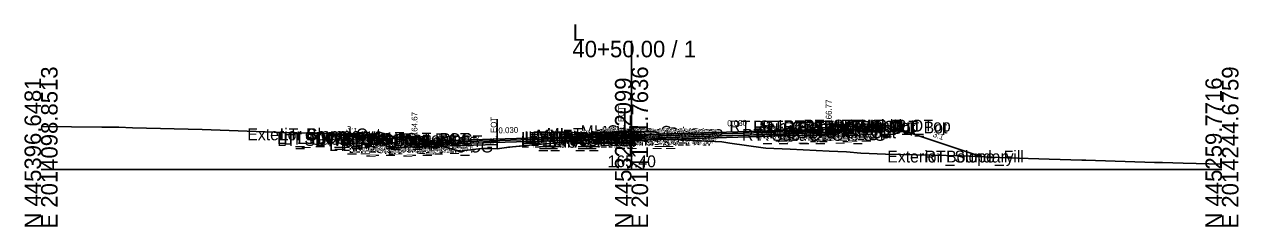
# Model space of a CAD drawing. Extents: x -26 to 4203, y -10 to 9526.
# Drawn here: x 2997.2 to 3202.8, y 490.3 to 524.6 of the extents above; entities that cross this region are included whole.
import ezdxf

# ---------------------------------------------------------------- set-up
doc = ezdxf.new("R2010")
doc.units = 0
for name, color, linetype in [('Default', 7, 'Continuous'), ('Exist CMT Pavement', 7, 'Continuous'), ('Exist Cross Section Cell', 7, 'Continuous'), ('Exist XS Center Line Elevation Label', 7, 'Continuous'), ('Exist XS Ground Line', 7, 'Continuous'), ('Prop CMT Conc Surface', 7, 'Continuous'), ('Prop CMT Concrete Structures', 7, 'Continuous'), ('Prop CMT Pvmt Course 1', 7, 'Continuous'), ('Prop CMT Pvmt Course 1 CG', 7, 'Continuous'), ('Prop CMT Pvmt Course 2', 7, 'Continuous'), ('Prop CMT Pvmt Course 3', 7, 'Continuous'), ('Prop CMT Pvmt Surface', 7, 'Continuous'), ('Prop CMT Slope Grass', 7, 'Continuous'), ('Prop CMT Subgrade Earthwork', 7, 'Continuous'), ('Prop XS Hydro Elevations', 7, 'Continuous'), ('Prop XS Label Text', 7, 'Continuous'), ('Prop XS SE Text', 7, 'Continuous'), ('Prop XS Side Slope Text', 7, 'Continuous'), ('Scratch_Level_0', 7, 'Continuous')]:
    doc.layers.add(name, color=color, linetype=linetype)

msp = doc.modelspace()

# ---------------------------------------------------------------- linework, layer by layer
at = {"layer": 'Exist CMT Pavement'}
for p, q in [((3079.85, 503.84), (3082.7, 504.14)), ((3082.7, 504.14), (3086.82, 504.5)), ((3086.82, 504.5), (3090.1, 504.8)), ((3090.1, 504.8), (3092.09, 504.95)), ((3092.09, 504.95), (3096.77, 505.26)), ((3096.77, 505.26), (3097.28, 505.29)), ((3097.28, 505.29), (3098.85, 505.39)), ((3077.27, 503.53), (3078.46, 503.71)), ((3078.46, 503.71), (3079.85, 503.84))]:
    msp.add_line(p, q, dxfattribs=at)
at = {"layer": 'Exist Cross Section Cell'}
for p, q in [((3100, 500), (3100, 521.83)), ((3000, 500), (3100, 500)), ((3100, 500), (3200, 500))]:
    msp.add_line(p, q, dxfattribs=at)
at = {"layer": 'Exist XS Ground Line'}
msp.add_lwpolyline([(3000, 507.28), (3010.27, 507.21), (3011.83, 507.19), (3013.19, 507.18), (3015.47, 507.09), (3027.31, 506.78), (3041.03, 506.27), (3047.94, 506.11), (3053.26, 505.85), (3063.03, 505.4), (3070.79, 503.11), (3071.75, 503.24), (3074.62, 503.55), (3075.76, 503.56), (3077.27, 503.53), (3078.46, 503.71), (3079.19, 503.77), (3079.85, 503.84), (3081.17, 503.98), (3082.7, 504.14), (3083.24, 504.19), (3086.82, 504.5), (3089.34, 504.74), (3090.1, 504.8), (3092.09, 504.95), (3093.62, 505.06), (3096.77, 505.26), (3097.28, 505.29), (3098.85, 505.39), (3100, 505.4), (3100.4, 505.4), (3100.97, 505.39), (3103.61, 505.31), (3103.96, 505.3), (3104.55, 505.22), (3105.08, 505.21), (3105.76, 505.17), (3115.32, 504.7), (3116.67, 504.5), (3122.32, 503.66), (3122.77, 503.64), (3126.89, 503.45), (3133.5, 503.11), (3136.41, 502.98), (3138.82, 502.8), (3142.99, 502.62), (3150.76, 502.43), (3155.9, 502.33), (3163.7, 502.01), (3170.71, 501.78), (3176.27, 501.59), (3176.96, 501.57), (3188.56, 501.22), (3189.95, 501.17), (3193.42, 501.07), (3200, 500.89)], dxfattribs=at)
at = {"layer": 'Prop CMT Conc Surface'}
for points in [[(3131.4, 506.79), (3133.4, 506.77)], [(3133.4, 506.77), (3133.4, 507.27), (3133.9, 507.27)], [(3137.9, 507.36), (3142.9, 507.46)], [(3058.75, 505.25), (3053.75, 505.35)], [(3063.25, 504.67), (3063.25, 505.16), (3062.75, 505.16)], [(3065.25, 504.8), (3063.25, 504.67)]]:
    msp.add_lwpolyline(points, dxfattribs=at)
at = {"layer": 'Prop CMT Concrete Structures'}
for points in [[(3104.62, 505.99), (3104.61, 506.15), (3103.86, 506.4), (3098.31, 506.51), (3092.76, 506.02), (3092.01, 505.77), (3092, 505.61)], [(3092, 505.61), (3104.62, 505.99)], [(3131.4, 506.79), (3133.4, 506.77), (3133.4, 507.27), (3133.9, 507.27)], [(3133.9, 507.27), (3133.9, 506.28), (3131.4, 506.21)], [(3131.4, 506.21), (3131.4, 506.79)], [(3142.9, 507.46), (3137.9, 507.36)], [(3137.9, 507.36), (3137.9, 507.03)], [(3137.9, 507.03), (3142.9, 507.13)], [(3142.9, 507.13), (3142.9, 507.46)], [(3053.75, 505.02), (3053.75, 505.35)], [(3053.75, 505.35), (3058.75, 505.25)], [(3058.75, 504.92), (3053.75, 505.02)], [(3058.75, 505.25), (3058.75, 504.92)], [(3065.25, 504.8), (3063.25, 504.67), (3063.25, 505.16), (3062.75, 505.16)], [(3062.75, 505.16), (3062.75, 504.15), (3065.25, 504.22)], [(3065.25, 504.22), (3065.25, 504.8)]]:
    msp.add_lwpolyline(points, dxfattribs=at)
at = {"layer": 'Prop CMT Pvmt Course 1'}
for points in [[(3092, 505.61), (3104.62, 505.99)], [(3104.62, 505.99), (3131.4, 506.79)], [(3131.4, 506.54), (3104.62, 505.74)], [(3104.62, 505.99), (3104.62, 505.74)], [(3104.62, 505.74), (3104.62, 505.99)], [(3131.4, 506.79), (3131.4, 506.54)], [(3092, 505.61), (3065.25, 504.8)], [(3065.25, 504.55), (3092, 505.36)], [(3065.25, 504.8), (3065.25, 504.55)], [(3104.62, 505.74), (3092, 505.36)], [(3092, 505.36), (3092, 505.61)], [(3092, 505.36), (3092, 505.61)]]:
    msp.add_lwpolyline(points, dxfattribs=at)
for points in [[(3092, 505.36), (3092, 505.48), (3092, 505.48), (3092, 505.36)], [(3104.62, 505.74), (3104.62, 505.86), (3104.62, 505.86), (3104.62, 505.74)]]:
    msp.add_lwpolyline(points, close=True, dxfattribs=at)
at = {"layer": 'Prop CMT Pvmt Course 1 CG'}
for points in [[(3131.4, 506.21), (3134.4, 506.3), (3134.72, 505.97)], [(3131.4, 505.87), (3131.4, 506.21)], [(3065.25, 504.22), (3062.25, 504.13), (3061.91, 503.79)], [(3065.25, 503.89), (3065.25, 504.22)], [(3134.72, 505.97), (3131.4, 505.87)], [(3061.91, 503.79), (3065.25, 503.89)]]:
    msp.add_lwpolyline(points, dxfattribs=at)
at = {"layer": 'Prop CMT Pvmt Course 2'}
for points in [[(3104.62, 505.74), (3131.4, 506.54)], [(3131.4, 506.21), (3104.62, 505.4)], [(3131.4, 506.54), (3131.4, 506.21)], [(3092, 505.36), (3065.25, 504.55)], [(3065.25, 504.22), (3092, 505.02)], [(3065.25, 504.55), (3065.25, 504.22)], [(3092, 505.36), (3104.62, 505.74)], [(3104.62, 505.4), (3092, 505.02)], [(3092, 505.02), (3092, 505.36)], [(3092, 505.02), (3092, 505.36)], [(3104.62, 505.74), (3104.62, 505.4)], [(3104.62, 505.4), (3104.62, 505.74)]]:
    msp.add_lwpolyline(points, dxfattribs=at)
at = {"layer": 'Prop CMT Pvmt Course 3'}
for points in [[(3104.62, 505.4), (3131.4, 506.21)], [(3131.4, 506.21), (3131.4, 505.87)], [(3092, 505.02), (3065.25, 504.22)], [(3065.25, 503.89), (3077.27, 504.25)], [(3065.25, 504.22), (3065.25, 503.89)], [(3092, 505.02), (3104.62, 505.4)], [(3104.62, 505.07), (3098.85, 504.9)], [(3131.4, 505.87), (3104.62, 505.07)], [(3104.62, 505.4), (3104.62, 505.07)], [(3104.62, 505.07), (3104.62, 505.4)]]:
    msp.add_lwpolyline(points, dxfattribs=at)
at = {"layer": 'Prop CMT Pvmt Surface'}
for points in [[(3092, 505.61), (3104.62, 505.99)], [(3104.62, 505.99), (3131.4, 506.79)], [(3092, 505.61), (3065.25, 504.8)]]:
    msp.add_lwpolyline(points, dxfattribs=at)
at = {"layer": 'Prop CMT Slope Grass'}
for points in [[(3133.9, 507.27), (3142.9, 507.45)], [(3142.9, 507.45), (3143.4, 507.46), (3159.18, 502.2)], [(3062.75, 505.16), (3053.25, 505.35), (3051.51, 505.94)]]:
    msp.add_lwpolyline(points, dxfattribs=at)
at = {"layer": 'Prop CMT Subgrade Earthwork'}
for p, q in [((3077.27, 504.25), (3077.27, 503.53)), ((3098.85, 504.9), (3098.85, 505.39))]:
    msp.add_line(p, q, dxfattribs=at)
for points in [[(3131.4, 505.87), (3134.72, 505.97), (3136.06, 507.31)], [(3065.25, 503.89), (3061.91, 503.79), (3060.48, 505.21)], [(3077.27, 504.25), (3065.25, 503.89)], [(3098.85, 504.9), (3104.62, 505.07)], [(3104.62, 505.07), (3131.4, 505.87)]]:
    msp.add_lwpolyline(points, dxfattribs=at)
at = {"layer": 'Prop XS Label Text'}
for p, q in [((3098.85, 510.39), (3098.85, 505.39)), ((3077.27, 508.53), (3077.27, 503.53))]:
    msp.add_line(p, q, dxfattribs=at)

# ---------------------------------------------------------------- texts
at = {"layer": 'Default'}
msp.add_text('-', height=0.0001, dxfattribs=at).set_placement((3000, 500))
at = {"layer": 'Exist Cross Section Cell'}
for s, p in [('L', (3090, 521.83)), ('40+50.00 / 1', (3090, 519.03))]:
    msp.add_text(s, height=2.8, dxfattribs=at).set_placement(p)
for s, p in [('E 2014098.8513', (3002.8, 490)), ('E 2014171.7636', (3102.8, 490)), ('E 2014244.6759', (3202.8, 490)), ('N 445396.6481', (3000, 490)), ('N 445328.2099', (3100, 490)), ('N 445259.7716', (3200, 490))]:
    msp.add_text(s, height=2.8, rotation=90, dxfattribs=at).set_placement(p)
at = {"layer": 'Exist XS Center Line Elevation Label'}
msp.add_text('165.40', height=2, dxfattribs=at).set_placement((3095.95, 500.4))
at = {"layer": 'Prop XS Hydro Elevations'}
for s, p in [('166.77', (3133.9, 507.77)), ('164.67', (3063.75, 505.67))]:
    msp.add_text(s, height=1, rotation=90, dxfattribs=at).set_placement(p)
at = {"layer": 'Prop XS Label Text'}
for p in [(3098.75, 506.41), (3077.17, 504.56)]:
    msp.add_text('E. EOT', height=1, rotation=90, dxfattribs=at).set_placement(p)
at = {"layer": 'Prop XS SE Text'}
for rotation, p in [(1.718, (3116.23, 507.33)), (1.7173, (3077.48, 506.13))]:
    msp.add_text('0.030', height=1, rotation=rotation, dxfattribs=at).set_placement(p)
at = {"layer": 'Prop XS Side Slope Text'}
for p in [(3051.59, 506.54), (3150.95, 505.58)]:
    msp.add_text('3:1', height=1, rotation=341.5651, dxfattribs=at).set_placement(p)
at = {"layer": 'Scratch_Level_0'}
for s, p in [('RT_Sub_Trench_Out_DLT', (3116.58, 506.31)), ('RT_CG_Top_Face', (3120.61, 506.27)), ('RT_CG_Top_BOC', (3122.13, 506.27)), ('RT_SDWK_In_Top', (3125.71, 506.36)), ('RT_SDWK_In_Bot', (3125.74, 506.03)), ('RT_SDWK_Out_Top', (3129.09, 506.46)), ('RT_SDWK_Out_Bot', (3129.12, 506.13)), ('RT_Shld_O', (3135.43, 506.45)), ('CSLP_Pnt', (3136.26, 506.46)), ('Exterior Boundary', (3034.93, 504.97)), ('LT_SDWK_Out_Top', (3039.99, 504.36)), ('LT_SDWK_Out_Bot', (3040.02, 504.02)), ('LT_Slope_Cut', (3040.43, 504.97)), ('LT_Sub_Trench_Out_DLT', (3041.05, 504.21)), ('LT_CSLP_Pnt', (3043.42, 504.36)), ('LT_SDWK_In_Top', (3046.61, 504.25)), ('LT_CG_Top_Face', (3050.51, 504.16)), ('LT_CG_Top_BOC', (3051.03, 504.16)), ('LT_PV2_OEEOP', (3081.31, 504.36)), ('LT_PV3_OEEOP', (3081.31, 504.02)), ('LT_PV1_OEEOP', (3081.87, 504.48)), ('LT_PV2_IEEOP', (3081.95, 504.36)), ('LT_PV1_IEEOP', (3082.52, 504.48)), ('LT_PV2_PGL1', (3082.88, 504.36)), ('LT_PV3_PGL1', (3082.88, 504.02)), ('LT_PV2_PGL', (3083.21, 504.36)), ('LT_PV1_PGL', (3083.78, 504.61)), ('MI_Face In', (3083.9, 504.77)), ('MI_Top In', (3085.61, 505.02)), ('MI_Crown', (3091.38, 505.51)), ('RT_Sub_OEEOP', (3093.79, 504.07)), ('RT_PV2_OEEOP', (3093.88, 504.74)), ('RT_PV3_OEEOP', (3093.88, 504.4)), ('RT_PV1_OEEOP', (3094.45, 504.86)), ('RT_PV2_IEEOP', (3094.53, 504.74)), ('MI_Face Out', (3094.88, 505.15)), ('MI_Top Out', (3095.09, 505.4)), ('RT_PV1_IEEOP', (3095.1, 504.86)), ('RT_PV2_PGL1', (3095.46, 504.74)), ('RT_PV3_PGL1', (3095.46, 504.4)), ('RT_PV2_PGL', (3095.79, 504.74)), ('RT_PV4_PGL', (3095.79, 504.07)), ('MI_Bot Out', (3095.88, 504.99)), ('RT_PV1_PGL', (3096.36, 504.99)), ('RT_Sub_OEOT_CG', (3118.72, 504.87)), ('RT_CG1_Shelf_Out', (3120.9, 505.3)), ('RT_CG_Bot_IE', (3121.26, 505.21)), ('RT_Sub_OEOT', (3121.43, 504.87)), ('RT_PV2_OEOT', (3121.52, 505.54)), ('RT_PV3_OEOT', (3121.52, 505.21)), ('RT_CG_Top_Gut', (3121.58, 505.77)), ('RT_PV1_OEOT', (3122.09, 505.79)), ('RT_CG_Bot_BOC', (3122.16, 505.28)), ('RT_Sub_OEOP', (3124.78, 504.97)), ('LT_SDWK_In_Bot', (3046.64, 503.92)), ('LT_CG1_Shelf_Out', (3048.8, 503.13)), ('LT_CG_Bot_BOC', (3051.07, 503.15)), ('LT_CG_Top_Gut', (3051.49, 503.67)), ('LT_Sub_OEOP', (3052.02, 502.79)), ('LT_Sub_OEOT_CG', (3052.62, 502.89)), ('LT_CG_Bot_IE', (3055.16, 503.22)), ('LT_Sub_OEOT', (3055.33, 502.89)), ('LT_PV2_OEOT', (3055.42, 503.55)), ('LT_PV3_OEOT', (3055.42, 503.22)), ('LT_PV1_OEOT', (3055.99, 503.8)), ('LT_Sub_OEEOP', (3081.21, 503.69)), ('LT_PV4_PGL', (3083.21, 503.69)), ('Exterior Boundary', (3143.32, 501.2)), ('RT_Slope_Fill', (3149.65, 501.2))]:
    msp.add_text(s, height=2, dxfattribs=at).set_placement(p)

doc.saveas('drawing.dxf')
